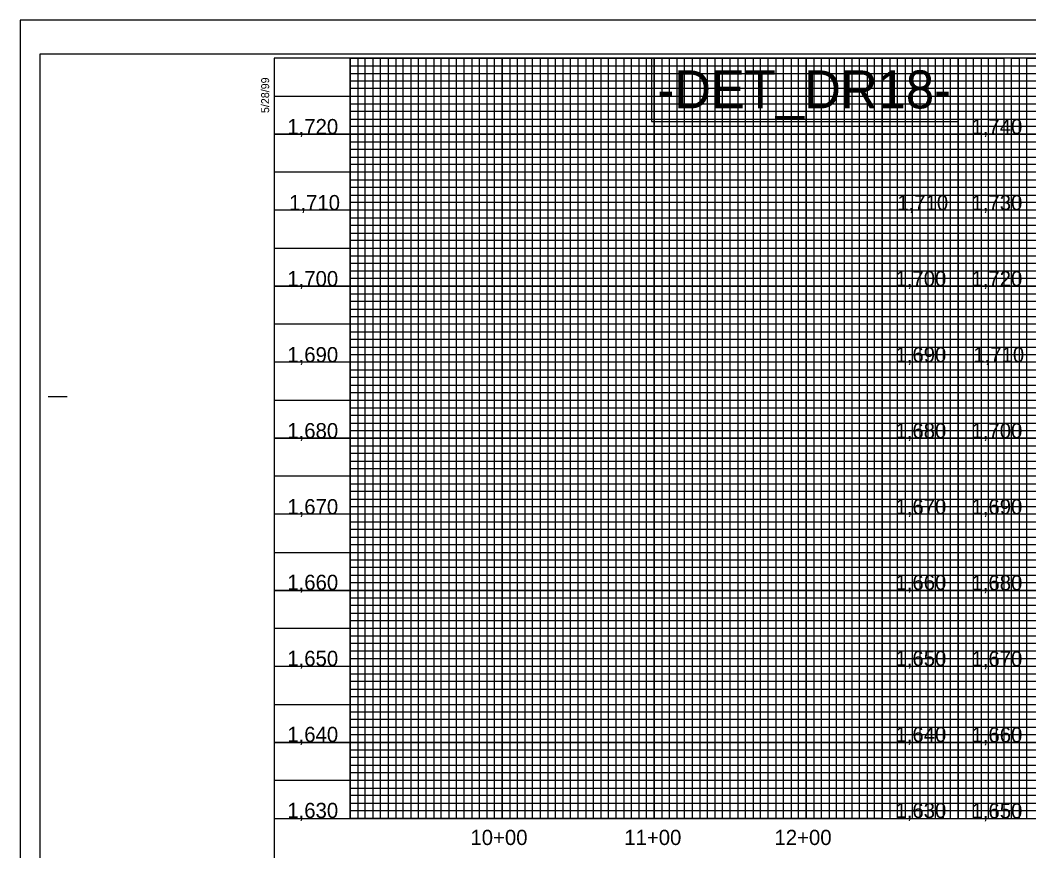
# Model space of a CAD drawing. Extents: x 505692 to 527456, y 415959 to 439886.
# Drawn here: x 505692 to 506355, y 439315 to 439861 of the extents above; entities that cross this region are included whole.
import ezdxf

# ---------------------------------------------------------------- set-up
doc = ezdxf.new("R2010")
doc.units = 0
for name, color, linetype in [('Exist Vertical Profile Vertical Axis Label', 7, 'Continuous'), ('Old_Level_1', 7, 'Continuous'), ('Prop Grid Mask', 7, 'Continuous'), ('Sheet Cutting Line CELL', 7, 'Continuous'), ('Sheet DOT Grid CELL', 7, 'Continuous'), ('Sheet Layout Profile Border Port 1', 7, 'Continuous'), ('Sheet Plot Border Inside CELL', 7, 'Continuous'), ('Sheet Plot Border Outside CELL', 7, 'Continuous'), ('Sheet Profile CELL', 7, 'Continuous'), ('Sheet Profile Grid Major CELL', 7, 'Continuous'), ('Sheet Profile Grid Middle CELL', 7, 'Continuous'), ('Sheet Profile Grid Minor CELL', 7, 'Continuous')]:
    doc.layers.add(name, color=color, linetype=linetype)

msp = doc.modelspace()

# ---------------------------------------------------------------- linework, layer by layer
at = {"layer": 'Prop Grid Mask'}
msp.add_lwpolyline([(506308.68, 439836.14), (506106.91, 439836.14), (506106.91, 439794.44), (506308.68, 439794.44)], close=True, dxfattribs=at)
at = {"layer": 'Sheet Cutting Line CELL'}
for p, q in [((507375.68, 439861.14), (505691.68, 439861.14)), ((505691.68, 439861.14), (505691.68, 438761.14))]:
    msp.add_line(p, q, dxfattribs=at)
at = {"layer": 'Sheet DOT Grid CELL'}
for p, q in [((505908.68, 439336.14), (505908.68, 439836.14)), ((505958.68, 439336.14), (505958.68, 439836.14)), ((506008.68, 439336.14), (506008.68, 439836.14)), ((506058.68, 439336.14), (506058.68, 439836.14)), ((506108.68, 439336.14), (506108.68, 439836.14)), ((506158.68, 439336.14), (506158.68, 439836.14)), ((506208.68, 439336.14), (506208.68, 439836.14)), ((506258.68, 439336.14), (506258.68, 439836.14)), ((506308.68, 439336.14), (506308.68, 439836.14)), ((507158.63, 439786.14), (505858.68, 439786.14)), ((507158.63, 439736.14), (505858.68, 439736.14)), ((507158.68, 439686.14), (505858.68, 439686.14)), ((507358.68, 439636.14), (505858.68, 439636.14)), ((507358.68, 439586.14), (505858.68, 439586.14)), ((507358.68, 439536.14), (505858.68, 439536.14)), ((507358.68, 439486.14), (505858.68, 439486.14)), ((507358.68, 439436.14), (505858.68, 439436.14)), ((507358.68, 439386.14), (505858.68, 439386.14))]:
    msp.add_line(p, q, dxfattribs=at)
at = {"layer": 'Sheet Layout Profile Border Port 1'}
msp.add_lwpolyline([(505908.68, 439836.14), (506258.68, 439836.14), (506258.68, 439336.14), (505908.68, 439336.14)], close=True, dxfattribs=at)
at = {"layer": 'Sheet Plot Border Inside CELL'}
msp.add_lwpolyline([(505704.68, 438783.59), (507371.18, 438783.59), (507371.18, 439838.69), (505704.68, 439838.69)], close=True, dxfattribs=at)
at = {"layer": 'Sheet Plot Border Outside CELL'}
msp.add_lwpolyline([(505691.68, 438761.14), (507375.68, 438761.14), (507375.68, 439861.14), (505691.68, 439861.14)], close=True, dxfattribs=at)
at = {"layer": 'Sheet Profile CELL'}
for p, q in [((506308.68, 439836.14), (506308.68, 439336.14)), ((505710.18, 439613.64), (505722.68, 439613.64)), ((505858.68, 439336.14), (507358.68, 439336.14))]:
    msp.add_line(p, q, dxfattribs=at)
msp.add_lwpolyline([(507358.68, 439836.14), (505858.68, 439836.14), (505858.68, 438786.14), (507358.68, 438786.14)], close=True, dxfattribs=at)
at = {"layer": 'Sheet Profile Grid Major CELL'}
for points in [[(505908.68, 439836.14), (505908.68, 439336.14), (505958.68, 439336.14), (505958.68, 439836.14), (506008.68, 439836.14), (506008.68, 439336.14), (506058.68, 439336.14), (506058.68, 439836.14), (506108.68, 439836.14), (506108.68, 439336.14), (506158.68, 439336.14), (506158.68, 439836.14), (506208.68, 439836.14), (506208.68, 439336.14), (506258.68, 439336.14), (506258.68, 439836.14), (506308.68, 439836.14), (506308.68, 439336.14), (506358.68, 439336.14)], [(505858.68, 439786.14), (507158.68, 439786.14)], [(507158.68, 439736.14), (505858.68, 439736.14), (505858.68, 439686.14), (507158.68, 439686.14)], [(507358.68, 439636.14), (505858.68, 439636.14), (505858.68, 439586.14), (507358.68, 439586.14)], [(507358.68, 439536.14), (505858.68, 439536.14), (505858.68, 439486.14), (507358.68, 439486.14)], [(507358.68, 439436.14), (505858.68, 439436.14), (505858.68, 439436.14), (505858.68, 439386.14), (507358.68, 439386.14)]]:
    msp.add_lwpolyline(points, dxfattribs=at)
at = {"layer": 'Sheet Profile Grid Middle CELL'}
msp.add_line((505858.68, 439811.14), (507158.63, 439811.14), dxfattribs=at)
for points in [[(505933.68, 439836.14), (505933.68, 439336.14), (505983.68, 439336.14), (505983.68, 439836.14), (506033.68, 439836.14), (506033.68, 439336.14), (506083.68, 439336.14), (506083.68, 439836.14), (506133.68, 439836.14), (506133.68, 439336.14), (506183.68, 439336.14), (506183.68, 439836.14), (506233.68, 439836.14), (506233.68, 439336.14), (506283.68, 439336.14), (506283.68, 439836.14), (506333.68, 439836.14), (506333.68, 439336.14), (506383.68, 439336.14)], [(507158.68, 439761.14), (505858.68, 439761.14), (505858.68, 439711.14), (507158.68, 439711.14)], [(507358.68, 439661.14), (505858.68, 439661.14), (505858.68, 439611.14), (507183.68, 439611.14)], [(507358.68, 439561.14), (505858.68, 439561.14), (505858.68, 439511.14), (507358.68, 439511.14)], [(507358.68, 439461.14), (505858.68, 439461.14), (505858.68, 439411.14), (507358.68, 439411.14)], [(507358.68, 439361.14), (505858.68, 439361.14)]]:
    msp.add_lwpolyline(points, dxfattribs=at)
at = {"layer": 'Sheet Profile Grid Minor CELL'}
for p, q in [((505908.68, 439831.14), (507158.68, 439831.14)), ((505908.68, 439826.14), (505908.68, 439826.14)), ((507158.68, 439826.14), (505908.68, 439825.79)), ((505908.68, 439821.14), (507158.68, 439821.14)), ((507158.63, 439701.14), (505908.68, 439701.14)), ((507158.68, 439696.14), (505908.68, 439696.14)), ((507158.68, 439691.14), (505908.68, 439691.14)), ((505908.68, 439681.14), (507158.68, 439681.14)), ((507158.68, 439676.14), (505908.68, 439676.14)), ((505908.68, 439671.14), (507308.68, 439671.14)), ((507308.68, 439651.14), (505908.68, 439651.14)), ((505908.68, 439646.14), (507308.68, 439646.14)), ((507308.68, 439626.14), (505908.68, 439626.14)), ((505908.68, 439621.14), (507308.68, 439621.14)), ((507308.68, 439601.14), (505908.68, 439601.14)), ((505908.68, 439596.14), (507308.68, 439596.14)), ((507308.68, 439591.14), (505908.68, 439591.14)), ((505908.68, 439581.14), (507308.68, 439581.14)), ((507308.68, 439576.14), (505908.68, 439576.14)), ((505908.68, 439571.14), (507308.68, 439571.14)), ((507308.68, 439566.14), (505908.68, 439566.14)), ((505908.68, 439556.14), (507308.68, 439556.14)), ((507308.68, 439551.14), (505908.68, 439551.14)), ((505908.68, 439546.14), (507308.68, 439546.14)), ((507308.68, 439541.14), (505908.68, 439541.14)), ((505908.68, 439531.14), (507308.68, 439531.14)), ((507308.68, 439526.14), (505908.68, 439526.14)), ((505908.68, 439521.14), (507308.68, 439521.14)), ((507308.68, 439516.14), (505908.68, 439516.14)), ((505908.68, 439506.14), (507308.68, 439506.14)), ((507308.68, 439501.14), (505908.68, 439501.14)), ((505908.68, 439496.14), (507308.68, 439496.14)), ((507308.68, 439491.14), (505908.68, 439491.14)), ((505908.68, 439481.14), (507308.68, 439481.14)), ((507308.68, 439476.14), (505908.68, 439476.14)), ((505908.68, 439471.14), (507308.68, 439471.14)), ((507308.68, 439466.14), (505908.68, 439466.14)), ((505908.68, 439456.14), (507308.68, 439456.14)), ((507308.68, 439451.14), (505908.68, 439451.14)), ((507308.68, 439446.14), (505908.68, 439446.14)), ((507308.68, 439441.14), (505908.68, 439441.14)), ((505908.68, 439431.14), (507308.68, 439431.14)), ((507308.68, 439426.14), (505908.68, 439426.14)), ((505908.68, 439421.14), (507308.68, 439421.14)), ((507308.68, 439416.14), (505908.68, 439416.14)), ((505908.68, 439406.14), (507308.68, 439406.14)), ((507308.68, 439401.14), (505908.68, 439401.14)), ((505908.68, 439396.14), (507308.68, 439396.14)), ((507308.68, 439391.14), (505908.68, 439391.14)), ((505908.68, 439381.14), (507308.68, 439381.14)), ((507308.68, 439376.14), (505908.68, 439376.14)), ((505908.68, 439371.14), (507308.68, 439371.14)), ((507308.68, 439366.14), (505908.68, 439366.14)), ((505908.68, 439356.14), (507308.68, 439356.14)), ((507308.68, 439351.14), (505908.68, 439351.14)), ((505908.68, 439346.14), (507308.68, 439346.14))]:
    msp.add_line(p, q, dxfattribs=at)
for points in [[(505913.68, 439836.14), (505913.68, 439336.14), (505918.68, 439336.14), (505918.68, 439836.14), (505923.68, 439836.14), (505923.68, 439336.14), (505928.68, 439336.14), (505928.68, 439836.14), (505938.68, 439836.14), (505938.68, 439336.14), (505943.68, 439336.14), (505943.68, 439836.14), (505948.68, 439836.14), (505948.68, 439336.14), (505953.68, 439336.14), (505963.68, 439336.14), (505968.68, 439336.14), (505968.68, 439836.14), (505973.68, 439836.14), (505973.68, 439336.14), (505978.68, 439336.14), (505978.68, 439836.14), (505988.68, 439836.14), (505988.68, 439336.14), (505993.68, 439336.14), (505993.68, 439836.14), (505998.68, 439836.14), (505998.68, 439336.14), (506003.68, 439336.14), (506003.68, 439836.14), (506013.68, 439836.14), (506013.68, 439336.14), (506018.68, 439336.14), (506018.68, 439836.14), (506023.68, 439836.14), (506023.68, 439336.14), (506028.68, 439336.14), (506028.68, 439836.14), (506038.68, 439836.14), (506038.68, 439336.14), (506043.68, 439336.14), (506043.68, 439836.14), (506048.68, 439836.14), (506048.68, 439336.14), (506053.68, 439336.14), (506053.68, 439836.14), (506063.68, 439836.14), (506063.68, 439336.14), (506068.68, 439336.14), (506068.68, 439836.14), (506073.68, 439836.14), (506073.68, 439336.14), (506078.68, 439336.14), (506078.68, 439836.14), (506088.68, 439836.14), (506088.68, 439336.14), (506093.68, 439336.14), (506093.68, 439836.14), (506098.68, 439836.14), (506098.68, 439336.14), (506103.68, 439336.14), (506103.68, 439836.14), (506113.68, 439836.14), (506113.68, 439336.14), (506118.68, 439336.14), (506118.68, 439836.14), (506123.68, 439836.14), (506123.68, 439336.14)], [(505953.68, 439336.14), (505953.68, 439836.14), (505963.68, 439836.14), (505963.68, 439336.14)], [(506123.68, 439336.14), (506128.68, 439336.14), (506128.68, 439836.14), (506138.68, 439836.14), (506138.68, 439336.14), (506143.68, 439336.14), (506143.68, 439836.14), (506148.68, 439836.14), (506148.68, 439336.14), (506153.68, 439336.14), (506153.68, 439836.14), (506163.68, 439836.14), (506163.68, 439336.14), (506168.68, 439336.14), (506168.68, 439836.14), (506173.68, 439836.14), (506173.68, 439336.14), (506178.68, 439336.14), (506178.68, 439836.14), (506188.68, 439836.14), (506188.68, 439336.14), (506193.68, 439336.14), (506193.68, 439836.14), (506198.68, 439836.14), (506198.68, 439336.14), (506203.68, 439336.14), (506203.68, 439836.14), (506213.68, 439836.14), (506213.68, 439336.14), (506218.68, 439336.14), (506218.68, 439836.14), (506223.68, 439836.14), (506223.68, 439336.14), (506228.68, 439336.14), (506228.68, 439836.14), (506238.68, 439836.14), (506238.68, 439336.14), (506243.68, 439336.14), (506243.68, 439836.14), (506248.68, 439836.14), (506248.68, 439336.14), (506253.68, 439336.14), (506253.68, 439836.14), (506263.68, 439836.14), (506263.68, 439336.14), (506268.68, 439336.14), (506268.68, 439836.14), (506273.68, 439836.14), (506273.68, 439336.14), (506278.68, 439336.14), (506278.68, 439836.14), (506288.68, 439836.14), (506288.68, 439336.14), (506293.68, 439336.14), (506293.68, 439836.14), (506298.68, 439836.14), (506298.68, 439336.14), (506303.68, 439336.14), (506303.68, 439836.14), (506313.68, 439836.14), (506313.68, 439336.14), (506318.68, 439336.14), (506318.68, 439836.14), (506323.68, 439836.14), (506323.68, 439336.14), (506328.68, 439336.14), (506328.68, 439836.14), (506338.68, 439836.14), (506338.68, 439336.14), (506343.68, 439336.14), (506343.68, 439836.14), (506348.68, 439836.14), (506348.68, 439336.14), (506353.68, 439336.14), (506353.68, 439836.14), (506363.68, 439836.14)], [(507158.68, 439816.14), (505908.68, 439816.14), (505908.68, 439806.14), (507158.68, 439806.14)], [(507158.63, 439801.14), (505908.68, 439801.14), (505908.68, 439796.14), (507158.68, 439796.14)], [(507158.68, 439791.14), (505908.68, 439791.14), (505908.68, 439781.14), (507158.68, 439781.14)], [(507158.68, 439776.14), (505908.68, 439776.14), (505908.68, 439771.14), (507158.68, 439771.14)], [(507158.68, 439766.14), (505908.68, 439766.14), (505908.68, 439756.14), (507158.68, 439756.14)], [(507158.68, 439751.14), (505908.68, 439751.14), (505908.68, 439746.14), (507158.68, 439746.14)], [(507158.68, 439741.14), (505908.68, 439741.14), (505908.68, 439731.14), (507158.68, 439731.14)], [(507158.68, 439726.04), (505908.78, 439726.04), (505908.78, 439721.14), (507158.68, 439721.14)], [(507158.68, 439716.14), (505908.68, 439716.14), (505908.68, 439706.14), (507158.68, 439706.14)], [(507308.68, 439666.14), (505908.68, 439666.14), (505908.68, 439656.14), (507308.68, 439656.14)], [(507308.68, 439641.14), (505908.68, 439641.14), (505908.68, 439631.14), (507308.68, 439631.14)], [(507308.68, 439616.14), (505908.68, 439616.14), (505908.68, 439606.14), (507308.68, 439606.14)], [(507308.68, 439341.14), (505908.68, 439341.14)]]:
    msp.add_lwpolyline(points, dxfattribs=at)

# ---------------------------------------------------------------- texts
at = {"layer": 'Exist Vertical Profile Vertical Axis Label'}
for s, p in [('1,720', (505867.37, 439786.14)), ('1,740', (506317.37, 439786.14)), ('1,710', (505868.57, 439736.14)), ('1,710', (506268.57, 439736.14)), ('1,730', (506317.37, 439736.14)), ('1,700', (505867.37, 439686.14)), ('1,700', (506267.37, 439686.14)), ('1,720', (506317.37, 439686.14)), ('1,690', (505867.37, 439636.14)), ('1,690', (506267.37, 439636.14)), ('1,710', (506318.57, 439636.14)), ('1,680', (505867.37, 439586.14)), ('1,680', (506267.37, 439586.14)), ('1,700', (506317.37, 439586.14)), ('1,670', (505867.37, 439536.14)), ('1,670', (506267.37, 439536.14)), ('1,690', (506317.37, 439536.14)), ('1,660', (505867.37, 439486.39)), ('1,660', (506267.37, 439486.39)), ('1,680', (506317.37, 439486.14)), ('1,650', (505867.37, 439436.39)), ('1,650', (506267.37, 439436.39)), ('1,670', (506317.37, 439436.14)), ('1,640', (505867.37, 439386.39)), ('1,640', (506267.37, 439386.39)), ('1,660', (506317.37, 439386.14)), ('1,630', (505867.37, 439336.39)), ('1,630', (506267.37, 439336.39)), ('1,650', (506317.37, 439336.14)), ('10+00', (505987.81, 439318.64)), ('11+00', (506089, 439318.64)), ('12+00', (506187.81, 439318.64))]:
    msp.add_text(s, height=10, dxfattribs=at).set_placement(p)
at = {"layer": 'Old_Level_1'}
msp.add_text('-DET_DR18-', height=25, dxfattribs=at).set_placement((506110.76, 439803.11))
at = {"layer": 'Sheet Profile CELL'}
msp.add_text('5/28/99', height=5.25, rotation=90, dxfattribs=at).set_placement((505855.44, 439800.06))

doc.saveas('drawing.dxf')
